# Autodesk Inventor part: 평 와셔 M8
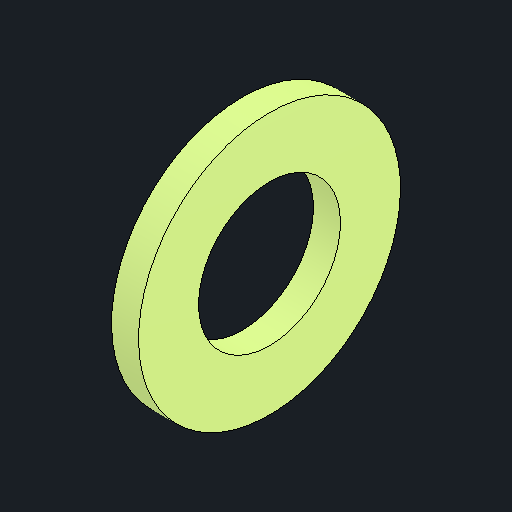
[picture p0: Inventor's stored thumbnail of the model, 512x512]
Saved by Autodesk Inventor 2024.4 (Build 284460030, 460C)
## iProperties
Created: 2026-08
Part Number: 평 와셔 M8
Material: 강철, 연강
Description: 평면 와셔
Document SubType Name: Modeling
Designer: user
Density: 7.85 g/cm^3
Appearance: 기본값
Author: jhkim
Sending System: Autodesk Inventor 2027
Preprocessor: ST-DEVELOPER v20.1
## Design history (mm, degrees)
feature "Solid1"
node "솔리드1"
